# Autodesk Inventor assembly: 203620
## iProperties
Created: 2008-01
Part Number: 203620
Document SubType Name: Assembly
Designer: jjohnson
Mass: 13.5013 g
Surface Area: 38.9292 cm^2
Volume: 5.08523 cm^3
Density: 2.655 g/cm^3
Author: jjohnson
